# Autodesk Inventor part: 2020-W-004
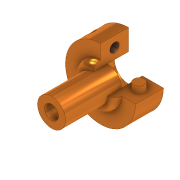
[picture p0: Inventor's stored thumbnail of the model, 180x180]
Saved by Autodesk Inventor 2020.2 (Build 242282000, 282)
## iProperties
Manager: www.cadconsulting.pl
Company: Fabian Stasiak CAD Consulting
Created: 2019-11
Part Number: 2020-W-004
Material: Złote
Document SubType Name: Modeling
Designer: F.Stasiak
Density: 19.3 g/cm^3
Appearance: Gorący metal 1600F
Author: F.Stasiak
Subject: Zbiór ćwiczeń. Autodesk Inventor 2020. Kurs podstawowy
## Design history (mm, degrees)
node "Opisy"
  node "Wymiar średnicy 1" dims "d29" = 20 (derived)
  node "Wymiar średnicy 2" dims "d31" = 40 (derived)
  node "Wymiar promienia 1" dims "d33" = 50 (derived)
  node "Wymiar liniowy 1" dims "d36" = 40 (derived)
  node "Wymiar średnicy 3" dims "d38" = 15 (derived)
  node "Opis otworu 1"
  node "Wymiar liniowy 2" dims "d44" = 10 (derived)
  node "Wymiar promienia 2" dims "d46" = 10 (derived)
  node "Wymiar liniowy 3" dims "d47" = 80 (derived)
  node "Wymiar liniowy 4" dims "d48" = 110 (derived)
sketch "Szkic1"
  geometry: C1 r 20 at (0, 0); C2 r 10 at (0, 0); 1 further point
  constraints: 2 centre point, 2 coincident
  dimensions: "d0" = 40 diameter of C1; "d1" = 20 diameter of C2
extrude "Wyciągnięcie proste1" new body sketch "Szkic1" distance "d2" = 80; taper "d3" = 0 deg
sketch "Szkic2"
  geometry: L1 (-20, 0)-(-20, 80) reference; L2 (-20, -30)-(-50, -30); L3 (-50, -30)-(-50, 10); L4 (-50, 10)-(-20, 10); L5 (-20, 10)-(-20, -30); L6 (0, -64.066)-(0, 104.011) reference; L7 (20, 0)-(-20, 0) reference; 3 further points
  constraints: 8 end point, 2 parallel, 1 horizontal, 1 perpendicular
  dimensions: "d6" = 40 distance of L2.end L3.end; "d7" = 100 diameter of L3 L6; "d8" = 40 diameter of L5 L6 (= d0); "d9" = 30 distance between parallel lines of L2 L7
revolve "Obrót1" sketch "Szkic2" stored, may be unused: angle "d10" = 270 deg
sketch "Szkic3"
  geometry: L1 (-30, 0)-(-40, 0) reference; L2 (-30, 0)-(0, 0) reference; L3 (0, 0)-(0, 30) reference; L4 (0, 30)-(-40, 30) reference; L5 (-40, 30)-(-40, 0) reference; L6 (0, 30)-(-40, 30) reference; L7 (-40, 30)-(0, 0); 2 further points
  constraints: 2 end point, 1 midpoint
hole "Otwór1" sketch "Szkic3" at (-20, 15) diameter "d11" = 13.3762; stored, may be unused: countersink angle "d15" = 90 deg, drill point angle "d17" = 118 deg; dims "d12" = 30, "d13" = 4, "d14" = 2, "d16" = 8
sketch "Szkic4"
  geometry: L1 (0, 40)-(0, 10) reference; L2 (0, 0)-(0, 10) reference; L3 (0, 0)-(30, 0) reference; L4 (30, 0)-(30, 40) reference; L5 (30, 40)-(0, 40) reference; L6 (0, 40)-(30, 0); C1 r 7.5 at (15, 20); 1 further point
  constraints: 2 end point, 1 centre point, 1 midpoint
  dimensions: "d18" = 15 diameter of C1
extrude "Wyciągnięcie proste2" join sketch "Szkic4" distance "d19" = 10; taper "d20" = 0 deg
fillet "Zaokrąglenie1" dims "d27" = 10
node "Bryła1"
node "Pętla rzutowana1"
node "Pętla rzutowana2"
other parameters: "d28" = 39.39649 (derived), "d30" = 29.68915 (derived), "d32" = 37.52825 (derived), "d34" = 0 (derived), "d37" = 22.77743 (derived), "d39" = 43.07297 (derived), "d45" = 12.05169 (derived)
